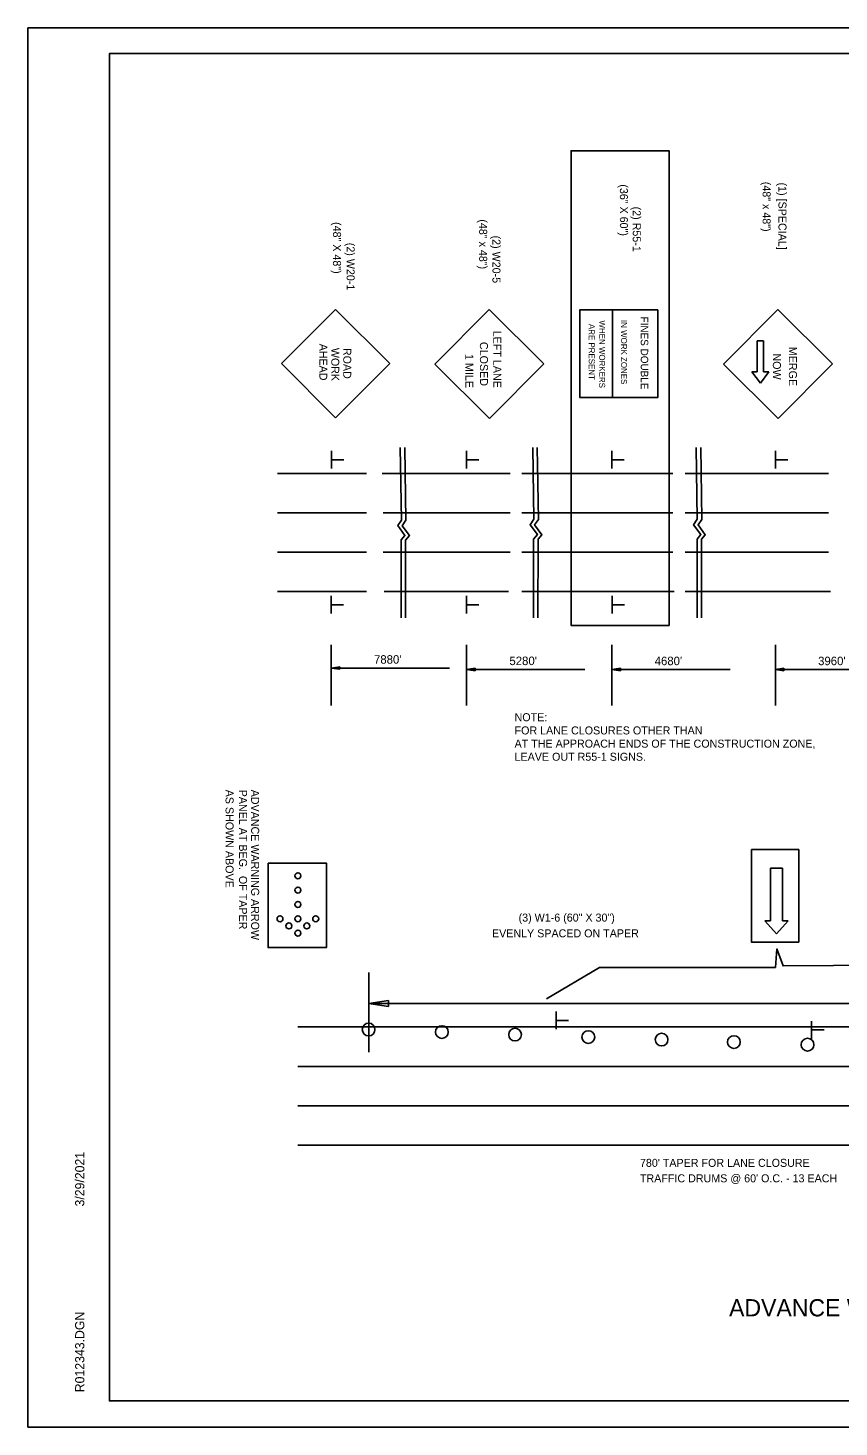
# Model space of a CAD drawing. Extents: x 1397271 to 1411271, y 376395 to 377888.
# Drawn here: x 1404271 to 1405137, y 376395 to 377888 of the extents above; entities that cross this region are included whole.
import ezdxf

# ---------------------------------------------------------------- set-up
doc = ezdxf.new("R2010")
doc.units = 0
for name, color, linetype in [('Default', 7, 'Continuous'), ('R_Border', 7, 'Continuous'), ('R_Border Notes', 7, 'Continuous'), ('R_MOT', 7, 'Continuous'), ('R_No Plot', 7, 'Continuous')]:
    doc.layers.add(name, color=color, linetype=linetype)

msp = doc.modelspace()

# ---------------------------------------------------------------- linework, layer by layer
at = {"layer": 'Default'}
for p, q in [((1404537.5, 377412.4), (1404632.3, 377412.4)), ((1404649.1, 377412.4), (1404785.7, 377412.4)), ((1404798.2, 377412.4), (1404959.3, 377412.4)), ((1404972.6, 377412.4), (1405125.4, 377412.4)), ((1404537.5, 377370.4), (1404632.3, 377370.4)), ((1404650.2, 377370.4), (1404785.7, 377370.4)), ((1404798.2, 377370.4), (1404959.3, 377370.4)), ((1404972.6, 377370.4), (1405125.4, 377370.4)), ((1404537.5, 377328.3), (1404632.3, 377328.3)), ((1404650.2, 377328.3), (1404785.7, 377328.3)), ((1404798.2, 377328.3), (1404959.3, 377328.3)), ((1404972.6, 377328.3), (1405125.4, 377328.3)), ((1404537.5, 377286.3), (1404632.3, 377286.3)), ((1404651.3, 377286.3), (1404784, 377286.3)), ((1404798.2, 377286.3), (1404960.7, 377286.3)), ((1404972.6, 377286.3), (1405127.6, 377286.3)), ((1404594.7, 377229.7), (1404594.7, 377164.8)), ((1404739.2, 377229.7), (1404739.2, 377164.8)), ((1404894.3, 377229.7), (1404894.3, 377164.8)), ((1405068.8, 377229.7), (1405068.8, 377164.8)), ((1404603.8, 377206.1), (1404594.7, 377204.8)), ((1404594.7, 377204.8), (1404720.9, 377204.8)), ((1404603.8, 377203.4), (1404594.7, 377204.8)), ((1404603.8, 377205.9), (1404596.2, 377204.8)), ((1404603.8, 377203.6), (1404596.2, 377204.8)), ((1404603.8, 377205.7), (1404597.8, 377204.8)), ((1404603.8, 377203.9), (1404597.8, 377204.8)), ((1404603.8, 377205.4), (1404599.3, 377204.8)), ((1404603.8, 377204.1), (1404599.3, 377204.8)), ((1404603.8, 377205.2), (1404600.8, 377204.8)), ((1404603.8, 377204.3), (1404600.8, 377204.8)), ((1404603.8, 377205), (1404602.3, 377204.8)), ((1404603.8, 377204.6), (1404602.3, 377204.8)), ((1404603.8, 377203.4), (1404603.8, 377206.1)), ((1404748.3, 377204.5), (1404739.2, 377203.2)), ((1404739.2, 377203.2), (1404865.4, 377203.2)), ((1404748.3, 377201.8), (1404739.2, 377203.2)), ((1404748.3, 377204.3), (1404740.7, 377203.2)), ((1404748.3, 377202), (1404740.7, 377203.2)), ((1404748.3, 377204.1), (1404742.3, 377203.2)), ((1404748.3, 377202.3), (1404742.3, 377203.2)), ((1404748.3, 377203.8), (1404743.8, 377203.2)), ((1404748.3, 377202.5), (1404743.8, 377203.2)), ((1404748.3, 377203.6), (1404745.3, 377203.2)), ((1404748.3, 377202.7), (1404745.3, 377203.2)), ((1404748.3, 377203.4), (1404746.8, 377203.2)), ((1404748.3, 377202.9), (1404746.8, 377203.2)), ((1404748.3, 377201.8), (1404748.3, 377204.5)), ((1404903.4, 377204.5), (1404894.3, 377203.2)), ((1404894.3, 377203.2), (1405020.5, 377203.2)), ((1404903.4, 377201.8), (1404894.3, 377203.2)), ((1404903.4, 377204.3), (1404895.8, 377203.2)), ((1404903.4, 377202), (1404895.8, 377203.2)), ((1404903.4, 377204.1), (1404897.4, 377203.2)), ((1404903.4, 377202.3), (1404897.4, 377203.2)), ((1404903.4, 377203.8), (1404898.9, 377203.2)), ((1404903.4, 377202.5), (1404898.9, 377203.2)), ((1404903.4, 377203.6), (1404900.5, 377203.2)), ((1404903.4, 377202.7), (1404900.5, 377203.2)), ((1404903.4, 377203.4), (1404902, 377203.2)), ((1404903.4, 377202.9), (1404902, 377203.2)), ((1404903.4, 377201.8), (1404903.4, 377204.5)), ((1405077.9, 377204.5), (1405068.8, 377203.2)), ((1405068.8, 377203.2), (1405195, 377203.2)), ((1405077.9, 377201.8), (1405068.8, 377203.2)), ((1405077.9, 377204.3), (1405070.3, 377203.2)), ((1405077.9, 377202), (1405070.3, 377203.2)), ((1405077.9, 377204.1), (1405071.9, 377203.2)), ((1405077.9, 377202.3), (1405071.9, 377203.2)), ((1405077.9, 377203.8), (1405073.4, 377203.2)), ((1405077.9, 377202.5), (1405073.4, 377203.2)), ((1405077.9, 377203.6), (1405074.9, 377203.2)), ((1405077.9, 377202.7), (1405074.9, 377203.2)), ((1405077.9, 377203.4), (1405076.4, 377203.2)), ((1405077.9, 377202.9), (1405076.4, 377203.2)), ((1405077.9, 377201.8), (1405077.9, 377204.5)), ((1404634.8, 376879.8), (1404634.8, 376794.7)), ((1404634.8, 376846.7), (1404655.8, 376849.9)), ((1405652, 376846.7), (1404634.8, 376846.7)), ((1404655.8, 376843.6), (1404634.8, 376846.7)), ((1404655.8, 376849.9), (1404655.8, 376843.6)), ((1404559.2, 376821.6), (1406315.8, 376821.6)), ((1404559.2, 376779.5), (1406315.8, 376779.5)), ((1404559.2, 376737.5), (1406315.8, 376737.5)), ((1404559.2, 376695.5), (1406315.8, 376695.5))]:
    msp.add_line(p, q, dxfattribs=at)
msp.add_lwpolyline([(1404955.3, 377250.3), (1404850.7, 377250.3), (1404850.7, 377757), (1404955.3, 377757)], close=True, dxfattribs=at)
for points in [[(1404668.4, 377440.2), (1404669.6, 377362.7), (1404665.7, 377356.8), (1404673.3, 377346.4), (1404669.3, 377341.5), (1404669.3, 377258.5)], [(1404673.3, 377440.2), (1404674.4, 377362.5), (1404670.5, 377356.6), (1404678.2, 377346.2), (1404674.1, 377341.3), (1404674.1, 377258.5)], [(1404809.8, 377440.2), (1404810.9, 377363.5), (1404807, 377357.7), (1404814.7, 377347.2), (1404810.6, 377342.4), (1404810.6, 377258.5)], [(1404814.6, 377440.2), (1404815.8, 377363.3), (1404811.8, 377357.5), (1404819.5, 377347), (1404815.5, 377342.2), (1404815.4, 377258.5)], [(1404984.2, 377440.2), (1404985.4, 377363.5), (1404981.5, 377357.7), (1404989.1, 377347.2), (1404985.1, 377342.4), (1404985.1, 377258.5)], [(1404989, 377440.2), (1404990.2, 377363.3), (1404986.3, 377357.5), (1404993.9, 377347), (1404989.9, 377342.2), (1404989.9, 377258.5)], [(1404824.3, 376851.8), (1404881, 376885.2), (1405068.8, 376885.2), (1405070.4, 376905), (1405077, 376886.8), (1405345.5, 376888.5), (1405390.3, 376848.3)]]:
    msp.add_lwpolyline(points, dxfattribs=at)
at = {"layer": 'R_Border'}
for p, q in [((1404358, 377860.7), (1406571.3, 377860.7)), ((1404358, 376422.5), (1404358, 377860.7)), ((1404358, 376422.5), (1404358, 376422.5)), ((1406571.3, 376422.5), (1404358, 376422.5))]:
    msp.add_line(p, q, dxfattribs=at)
at = {"layer": 'R_MOT'}
for p, q in [((1404541.6, 377529.7), (1404599.4, 377587.5)), ((1404599.4, 377587.5), (1404657.2, 377529.7)), ((1404705.2, 377529.2), (1404763.3, 377587.5)), ((1404763.3, 377587.5), (1404821.5, 377529.4)), ((1404894.9, 377493.6), (1404894.9, 377587)), ((1405013.5, 377529.2), (1405071.5, 377587.5)), ((1405071.5, 377587.5), (1405129.8, 377529.4)), ((1405049.4, 377520.8), (1405049.4, 377554.1)), ((1405049.4, 377554.1), (1405056.2, 377554.1)), ((1405056.2, 377554.1), (1405056.2, 377520.8)), ((1404599.4, 377471.9), (1404541.6, 377529.7)), ((1404657.2, 377529.7), (1404599.4, 377471.9)), ((1404821.5, 377529.4), (1404763.5, 377471.1)), ((1405129.8, 377529.4), (1405071.8, 377471.1)), ((1404763.5, 377471.1), (1404705.2, 377529.2)), ((1405071.8, 377471.1), (1405013.5, 377529.2)), ((1405052.8, 377509), (1405043.7, 377520.8)), ((1405043.7, 377520.8), (1405049.4, 377520.8)), ((1405061.8, 377520.8), (1405052.8, 377509)), ((1405056.2, 377520.8), (1405061.8, 377520.8)), ((1404594.9, 377417.6), (1404594.9, 377436.5)), ((1404595.2, 377427), (1404608.1, 377427)), ((1404739.2, 377417.6), (1404739.2, 377436.5)), ((1404739.5, 377427), (1404752.4, 377427)), ((1404894.3, 377417.6), (1404894.3, 377436.5)), ((1404894.6, 377427), (1404907.5, 377427)), ((1405068.8, 377417.6), (1405068.8, 377436.5)), ((1405069.1, 377427), (1405082, 377427)), ((1404594.7, 377262.8), (1404594.7, 377281.7)), ((1404739.2, 377262.8), (1404739.2, 377281.7)), ((1404894.5, 377262.8), (1404894.5, 377281.7)), ((1404595, 377272.2), (1404607.9, 377272.2)), ((1404739.5, 377272.2), (1404752.4, 377272.2)), ((1404894.7, 377272.2), (1404907.7, 377272.2)), ((1405063.6, 376934.9), (1405063.6, 376991.3)), ((1405063.6, 376991.3), (1405076.2, 376991.3)), ((1405076.2, 376991.3), (1405076.2, 376934.9)), ((1405069.9, 376921.2), (1405057.4, 376934.9)), ((1405057.4, 376934.9), (1405063.6, 376934.9)), ((1405082.5, 376934.9), (1405069.9, 376921.2)), ((1405076.2, 376934.9), (1405082.5, 376934.9)), ((1404834.9, 376838.1), (1404834.9, 376819.2)), ((1404835.1, 376828.7), (1404848, 376828.7)), ((1405107.4, 376827.8), (1405107.4, 376808.9)), ((1405107.6, 376818.4), (1405120.6, 376818.4))]:
    msp.add_line(p, q, dxfattribs=at)
for points in [[(1404943.3, 377587), (1404859.9, 377587), (1404859.9, 377493.6), (1404943.3, 377493.6)], [(1405043.1, 377011), (1405043.1, 376912.2), (1405093.6, 376912.2), (1405093.6, 377011)], [(1404527.3, 376996.5), (1404527.3, 376906.4), (1404589.6, 376906.4), (1404589.6, 376996.5)]]:
    msp.add_lwpolyline(points, close=True, dxfattribs=at)
for centre, radius in [((1404559.2, 376983), 3.17), ((1404559.2, 376967.7), 3.17), ((1404559.2, 376952.4), 3.17), ((1404540.1, 376937.1), 3.17), ((1404549.6, 376929.5), 3.17), ((1404559.2, 376937.1), 3.17), ((1404568.7, 376929.5), 3.17), ((1404578.2, 376937.1), 3.17), ((1404559.2, 376921.8), 3.17), ((1404634.6, 376818.9), 6.8), ((1404712.8, 376816.2), 6.8), ((1404790.9, 376813.5), 6.8), ((1404869.1, 376810.8), 6.8), ((1404947.3, 376808.2), 6.8), ((1405024.4, 376805.5), 6.8), ((1405103, 376802.7), 6.8)]:
    msp.add_circle(centre, radius, dxfattribs=at)
at = {"layer": 'R_No Plot'}
for p, q in [((1404271.2, 377888), (1406604.6, 377888)), ((1404271.2, 376394.6), (1406604.6, 376394.6))]:
    msp.add_line(p, q, dxfattribs=at)
for points in [[(1404271.1, 377888), (1406604.6, 377888), (1406604.6, 376394.6), (1404271.1, 376394.6)], [(1405995.5, 377860.7), (1405995.5, 377791.6), (1406245.6, 377791.6), (1406245.6, 377771.1), (1406408, 377771.1), (1406408, 377600.8), (1406571.3, 377600.8), (1406571.3, 376422.5), (1404358, 376422.5), (1404358, 377860.7)]]:
    msp.add_lwpolyline(points, close=True, dxfattribs=at)

# ---------------------------------------------------------------- texts
at = {"layer": 'Default'}
for s, height, p in [("7880'", 9.07, (1404640.4, 377209.4)), ("5280'", 9.07, (1404784.9, 377207.9)), ("4680'", 9.07, (1404939.9, 377207.8)), ("3960'", 9.07, (1405114.3, 377207.8)), ('NOTE:', 8.54, (1404790.4, 377148)), ('FOR LANE CLOSURES OTHER THAN ', 8.54, (1404790.4, 377133.9)), ('AT THE APPROACH ENDS OF THE CONSTRUCTION ZONE,', 8.54, (1404790.4, 377119.8)), ('LEAVE OUT R55-1 SIGNS.', 8.54, (1404790.4, 377105.8)), ("780' TAPER FOR LANE CLOSURE", 8.54, (1404924.2, 376672.3)), ("TRAFFIC DRUMS @ 60' O.C. - 13 EACH", 8.54, (1404924.2, 376655.8))]:
    msp.add_text(s, height=height, dxfattribs=at).set_placement(p)
for s, rotation, p in [('AS SHOWN ABOVE', 270, (1404482, 377074.9)), ('PANEL AT BEG.  OF TAPER', 270, (1404496.4, 377074.9)), ('ADVANCE WARNING ARROW', 270, (1404509.3, 377074.9)), ('(3) W1-6 (60" X 30")', 0.0075, (1404794.7, 376934.1)), ('EVENLY SPACED ON TAPER', 0.0075, (1404766.3, 376917.3))]:
    msp.add_text(s, height=8.54, rotation=rotation, dxfattribs=at).set_placement(p)
at = {"layer": 'R_Border'}
for s, p in [('3/29/2021', (1404331.3, 376630)), ('R012343.DGN', (1404331.3, 376431.7))]:
    msp.add_text(s, height=9.8, rotation=90, dxfattribs=at).set_placement(p)
at = {"layer": 'R_Border Notes'}
msp.add_text('ADVANCE WARNING SIGNS & TYPICAL TRAFFIC DRUM LAYOUT', height=18.375, dxfattribs=at).set_placement((1405019.3, 376512.7))
at = {"layer": 'R_MOT'}
for s, height, rotation, p in [('(36" X 60")', 8.54, 270, (1404902.8, 377721.1)), ('(48" x 48")', 8.54, 270, (1405055.1, 377723.8)), ('(1) [SPECIAL]', 8.54, 270, (1405072, 377723)), ('(2) R55-1', 8.54, 270, (1404916.5, 377697.3)), ('(48" X 48")', 8.54, 270, (1404596.7, 377680.8)), ('(48" x 48")', 8.54, 270, (1404752.6, 377683.7)), ('(2) W20-5', 8.54, 270, (1404766.8, 377666.4)), ('(2) W20-1', 8.54, 270, (1404611.2, 377658.7)), ('WHEN WORKERS', 6.34, 270, (1404880.7, 377575.8)), ('IN WORK ZONES', 6.339, 270, (1404904, 377576.3)), ('FINES DOUBLE', 7.925, 270, (1404925.1, 377579.9)), ('LEFT LANE', 8.57, 270.1004, (1404767.6, 377564.9)), ('ARE PRESENT', 6.34, 270, (1404869.6, 377572.1)), (' AHEAD', 8.51, 270.0006, (1404582.1, 377554.1)), ('WORK', 8.51, 270, (1404594.8, 377546.5)), ('ROAD', 8.51, 270.0004, (1404607.6, 377546.4)), ('CLOSED', 8.57, 270.1003, (1404753.4, 377552.9)), ('MERGE', 8.57, 270.1004, (1405083.1, 377547.7)), ('1 MILE', 8.62, 270.0006, (1404737.8, 377540.1)), ('NOW', 8.57, 270.1003, (1405066, 377540.6))]:
    msp.add_text(s, height=height, rotation=rotation, dxfattribs=at).set_placement(p)

doc.saveas('drawing.dxf')
